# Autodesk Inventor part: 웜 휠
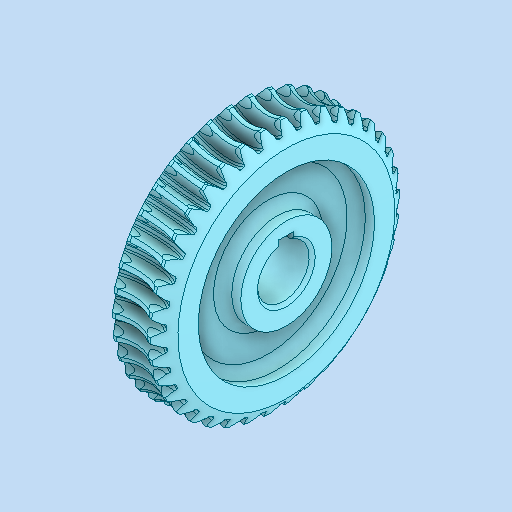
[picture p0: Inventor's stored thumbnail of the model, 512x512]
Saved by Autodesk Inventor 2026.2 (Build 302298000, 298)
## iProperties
Created: 2026-01
Part Number: 웜 휠
Material: 강철, 합금
Document SubType Name: Modeling
Designer: PC2-07
Density: 7.73 g/cm^3
Appearance: 기본값
Author: jhkim
Sending System: Autodesk Inventor 2026
Preprocessor: ST-DEVELOPER v20.1
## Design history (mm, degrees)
feature "솔리드1"
node "솔리드2"
